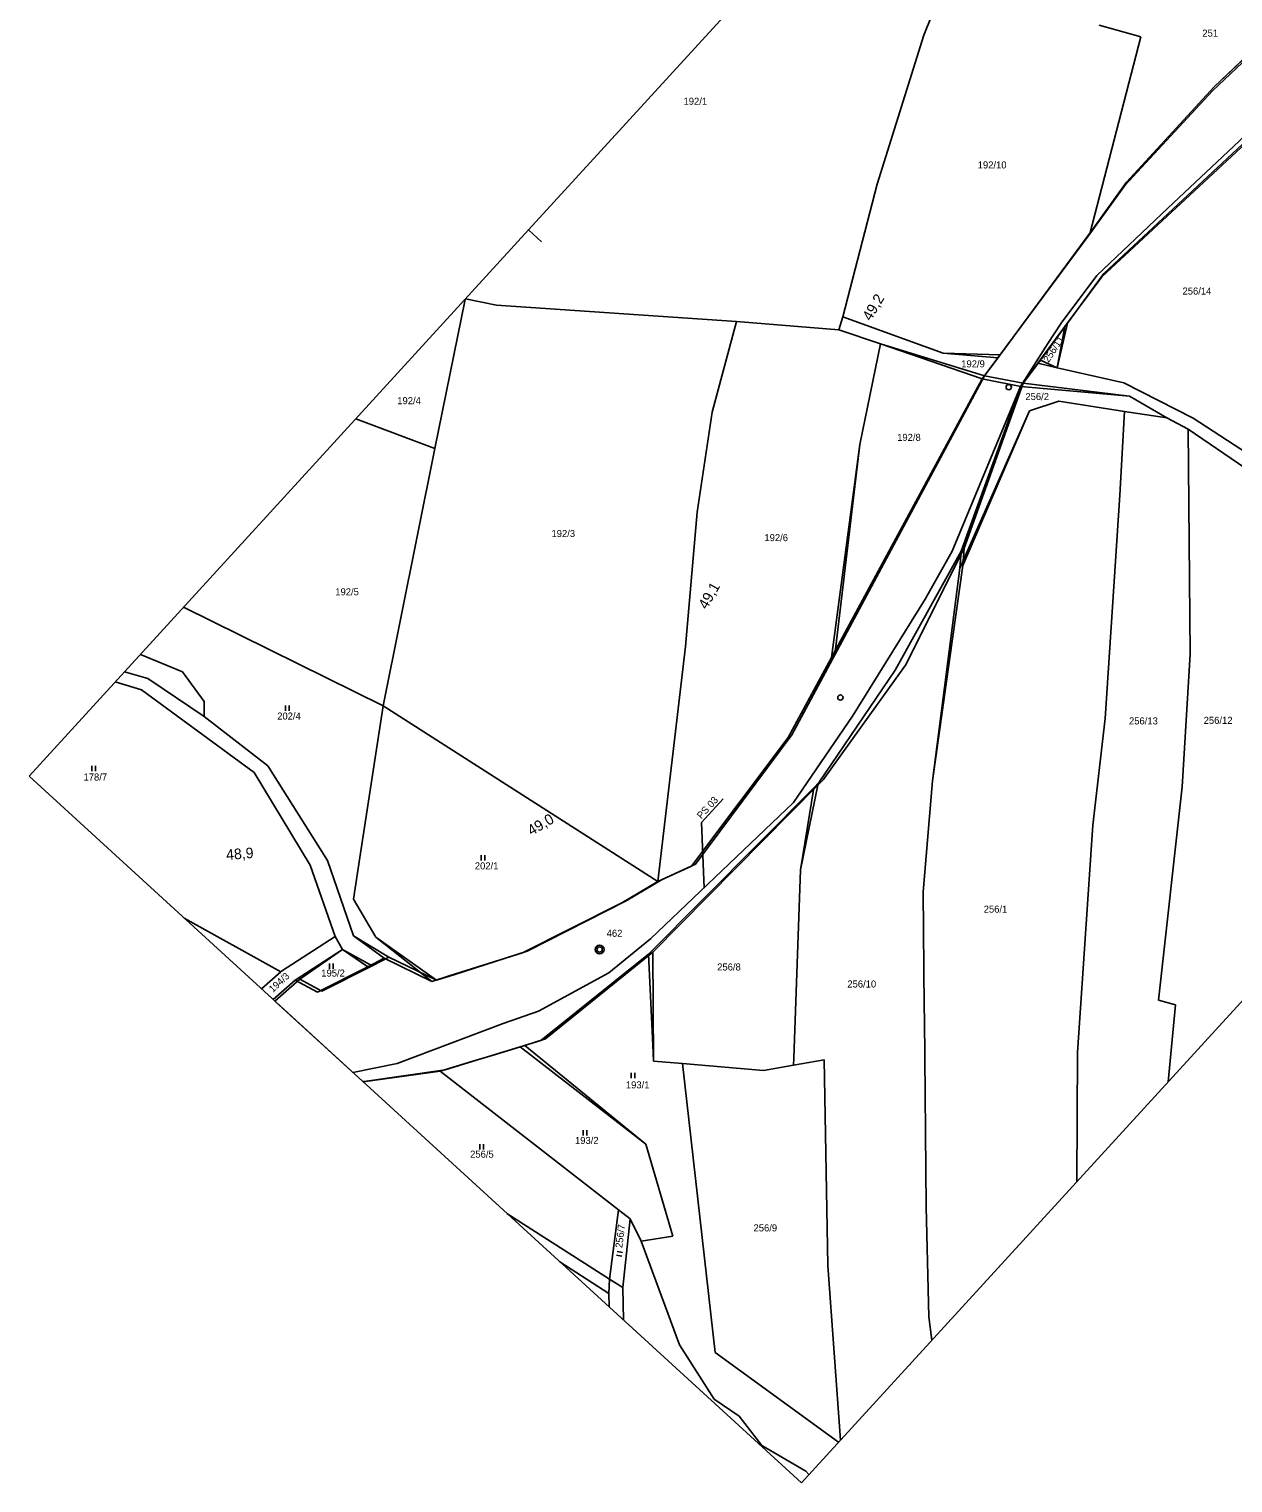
# Model space of a CAD drawing. Extents: x -678683 to -677755, y -1006946 to -1005971.
# Drawn here: x -678683 to -678341.4, y -1006946.3 to -1006533.9 of the extents above; entities that cross this region are included whole.
import ezdxf

# ---------------------------------------------------------------- set-up
doc = ezdxf.new("R2010")
doc.units = 0
for name, color, linetype in [('I_2_4_předběžný_vykres - SŽDC', 7, 'Continuous'), ('kilometráž - Vrstva 7', 7, 'Continuous'), ('koor - SSZT_nové', 7, 'Continuous'), ('MapaKN - Mladejov+Strelec_dosavani+nova_situace - Vrstva 1', 7, 'Continuous'), ('MapaKN - Mladejov+Strelec_dosavani+nova_situace - Vrstva 11', 7, 'Continuous'), ('MapaKN - Mladejov+Strelec_dosavani+nova_situace - Vrstva 18', 7, 'Continuous'), ('MapaKN - Mladejov+Strelec_dosavani+nova_situace - Vrstva 25', 7, 'Continuous'), ('MapaKN - původní vrstava 1', 7, 'Continuous'), ('popis', 7, 'Continuous'), ('ramy - Sekce lichá', 7, 'Continuous')]:
    doc.layers.add(name, color=color, linetype=linetype)

msp = doc.modelspace()

# ---------------------------------------------------------------- linework, layer by layer
at = {"layer": 'I_2_4_předběžný_vykres - SŽDC'}
for p, q in [((-678328.04, -1006532.61), (-678346.7, -1006550.29)), ((-678346.7, -1006550.29), (-678371.57, -1006577.31)), ((-678377.98, -1006603.23), (-678337.35, -1006565.27)), ((-678371.57, -1006577.31), (-678381.45, -1006591.04)), ((-678388.38, -1006617.35), (-678377.98, -1006603.23)), ((-678396.04, -1006627.76), (-678388.38, -1006617.35)), ((-678407.43, -1006626.27), (-678411.85, -1006632.26)), ((-678400.89, -1006634.35), (-678396.04, -1006627.76)), ((-678411.85, -1006632.26), (-678454.36, -1006711.39)), ((-678417.64, -1006681.12), (-678400.89, -1006634.35)), ((-678400.89, -1006634.35), (-678411.85, -1006632.26)), ((-678411.85, -1006632.26), (-678400.89, -1006634.35)), ((-678434.3, -1006714.32), (-678417.64, -1006681.12)), ((-678454.36, -1006711.39), (-678466.57, -1006734.1)), ((-678457.66, -1006746.82), (-678434.3, -1006714.32)), ((-678466.57, -1006734.1), (-678493.85, -1006770.72)), ((-678459.21, -1006748.39), (-678457.66, -1006746.82)), ((-678505.95, -1006795.71), (-678459.21, -1006748.39)), ((-678493.85, -1006770.72), (-678503.38, -1006775.08)), ((-678503.38, -1006775.08), (-678513.57, -1006781.17)), ((-678513.57, -1006781.17), (-678541.67, -1006795.44)), ((-678541.67, -1006795.44), (-678562.49, -1006802.11)), ((-678536.44, -1006820.34), (-678505.95, -1006795.71)), ((-678585.58, -1006799.58), (-678599.89, -1006806.81)), ((-678580.93, -1006797.11), (-678585.58, -1006799.58)), ((-678567.41, -1006803.68), (-678580.93, -1006797.11)), ((-678606.18, -1006803.39), (-678613.24, -1006809.59)), ((-678599.89, -1006806.81), (-678606.18, -1006803.39)), ((-678562.49, -1006802.11), (-678567.41, -1006803.68)), ((-678613.24, -1006809.59), (-678588.31, -1006832.39)), ((-678542.33, -1006822.15), (-678536.44, -1006820.34)), ((-678555.75, -1006826.28), (-678551.55, -1006824.99)), ((-678551.55, -1006824.99), (-678542.33, -1006822.15)), ((-678587.94, -1006832.39), (-678564.93, -1006829.1)), ((-678564.93, -1006829.1), (-678555.75, -1006826.28)), ((-678588.31, -1006832.39), (-678587.94, -1006832.39))]:
    msp.add_line(p, q, dxfattribs=at)
msp.add_lwpolyline([(-678381.45, -1006591.04), (-678381.96, -1006591.73), (-678407.43, -1006626.27)], dxfattribs=at)
at = {"layer": 'kilometráž - Vrstva 7'}
for centre, radius in [((-678405, -1006635.46), 0.75), ((-678452.78, -1006723.49), 0.75), ((-678521.09, -1006794.96), 1.25), ((-678521.09, -1006794.96), 0.752)]:
    msp.add_circle(centre, radius, dxfattribs=at)
at = {"layer": 'koor - SSZT_nové'}
for points in [[(-678506.62, -1006791.94), (-678466.12, -1006753.23), (-678449.33, -1006728.75), (-678428.75, -1006695.61), (-678421.07, -1006681.97), (-678401.67, -1006635.24), (-678393.87, -1006623.11), (-678390.13, -1006617.26), (-678380, -1006603.76), (-678359.84, -1006584.7), (-678339.66, -1006565.68), (-678276.52, -1006503.93), (-678276.52, -1006503.93)], [(-678591.08, -1006829.86), (-678578.56, -1006827.33), (-678548.42, -1006815.94), (-678538.41, -1006812.42), (-678518.43, -1006801.56), (-678506.62, -1006791.94), (-678506.62, -1006791.94)]]:
    msp.add_lwpolyline(points, dxfattribs=at)
at = {"layer": 'MapaKN - Mladejov+Strelec_dosavani+nova_situace - Vrstva 1'}
for points in [[(-678420.43, -1006513.99), (-678429.12, -1006535.58)], [(-678379.35, -1006532.79), (-678367.5, -1006536.07)], [(-678429.12, -1006535.58), (-678442.37, -1006577.92)], [(-678367.5, -1006536.07), (-678382.03, -1006592)], [(-678442.37, -1006577.92), (-678452.11, -1006615.47)], [(-678559.26, -1006610.55), (-678567.8, -1006652.87)], [(-678550.36, -1006612.19), (-678559.15, -1006610.43)], [(-678482.29, -1006616.83), (-678550.36, -1006612.19)], [(-678452.11, -1006615.47), (-678453.19, -1006619.16)], [(-678423.65, -1006625.83), (-678452.11, -1006615.47)], [(-678482.29, -1006616.83), (-678489.11, -1006642.57)], [(-678453.19, -1006619.16), (-678482.29, -1006616.83)], [(-678453.19, -1006619.16), (-678441.4, -1006623.21)], [(-678441.4, -1006623.21), (-678447.23, -1006651.72)], [(-678372.38, -1006634.27), (-678391.25, -1006629.93)], [(-678352.67, -1006644.27), (-678372.38, -1006634.27)], [(-678390.75, -1006639.42), (-678399.16, -1006642.13)], [(-678372.18, -1006642.32), (-678390.75, -1006639.42)], [(-678370.74, -1006638.02), (-678360.18, -1006644.19)], [(-678489.11, -1006642.57), (-678493.38, -1006670.87)], [(-678373.53, -1006666.09), (-678372.18, -1006642.32)], [(-678360.18, -1006644.19), (-678372.18, -1006642.32)], [(-678354.06, -1006647.41), (-678360.18, -1006644.19)], [(-678337.28, -1006654.25), (-678352.67, -1006644.27)], [(-678567.8, -1006652.87), (-678590.28, -1006644.46)], [(-678353.55, -1006711.22), (-678354.06, -1006647.41)], [(-678354.06, -1006647.41), (-678337.76, -1006658.53)], [(-678567.8, -1006652.87), (-678582.53, -1006725.83)], [(-678377.6, -1006729.48), (-678373.53, -1006666.09)], [(-678493.38, -1006670.87), (-678496.7, -1006709.02)], [(-678639.15, -1006697.89), (-678582.53, -1006725.83)], [(-678496.7, -1006709.02), (-678504.57, -1006775.64)], [(-678639.46, -1006716.2), (-678651.38, -1006711.26)], [(-678355.8, -1006748.81), (-678353.55, -1006711.22)], [(-678655.87, -1006716.16), (-678649.31, -1006718.06)], [(-678649.31, -1006718.06), (-678633.3, -1006728.9)], [(-678633.27, -1006724.57), (-678639.46, -1006716.2)], [(-678658.53, -1006719.07), (-678651.04, -1006721.27)], [(-678651.04, -1006721.27), (-678619.06, -1006744.74)], [(-678633.3, -1006728.9), (-678633.27, -1006724.57)], [(-678582.53, -1006725.83), (-678589.14, -1006768.88)], [(-678582.53, -1006725.83), (-678504.57, -1006775.64)], [(-678633.3, -1006728.9), (-678615.21, -1006742.84)], [(-678381.19, -1006759.69), (-678377.6, -1006729.48)], [(-678615.21, -1006742.84), (-678598.31, -1006769.67)], [(-678619.06, -1006744.74), (-678603.23, -1006770.99)], [(-678426.68, -1006747.13), (-678429.29, -1006778.6)], [(-678362.53, -1006809.3), (-678355.8, -1006748.81)], [(-678385.49, -1006824.2), (-678381.19, -1006759.69)], [(-678603.23, -1006770.99), (-678596.1, -1006791.26)], [(-678598.31, -1006769.67), (-678590.92, -1006791.09)], [(-678589.14, -1006768.88), (-678590.95, -1006780.65)], [(-678465.97, -1006825.71), (-678464.06, -1006772.32)], [(-678429.29, -1006778.6), (-678429.05, -1006811.35)], [(-678590.95, -1006780.65), (-678584.59, -1006791.47)], [(-678611.57, -1006801.32), (-678638.98, -1006786.04)], [(-678596.1, -1006791.26), (-678611.34, -1006801.12)], [(-678594.01, -1006794.95), (-678596.1, -1006791.26)], [(-678506.03, -1006822.05), (-678507.21, -1006796.26)], [(-678611.57, -1006801.32), (-678617.05, -1006806.1)], [(-678611.34, -1006801.12), (-678611.57, -1006801.32)], [(-678357.73, -1006810.61), (-678362.53, -1006809.3)], [(-678429.05, -1006811.35), (-678428.88, -1006814.85)], [(-678359.8, -1006832.53), (-678357.73, -1006810.61)], [(-678428.43, -1006867.92), (-678428.88, -1006814.85)], [(-678507.96, -1006850.17), (-678543.67, -1006822.58)], [(-678505.82, -1006826.67), (-678506.03, -1006822.05)], [(-678465.97, -1006825.71), (-678466.07, -1006827.77)], [(-678385.66, -1006860.8), (-678385.49, -1006824.2)], [(-678566.3, -1006829.46), (-678515.73, -1006868.76)], [(-678497.6, -1006827.29), (-678505.82, -1006826.67)], [(-678488.35, -1006909.3), (-678497.6, -1006827.29)], [(-678474.56, -1006829.3), (-678497.6, -1006827.29)], [(-678466.07, -1006827.77), (-678474.56, -1006829.3)], [(-678457.4, -1006826.21), (-678466.07, -1006827.77)], [(-678457.31, -1006831.43), (-678457.4, -1006826.21)], [(-678456.35, -1006884.57), (-678457.31, -1006831.43)], [(-678500.3, -1006876.27), (-678507.96, -1006850.17)], [(-678547.38, -1006869.83), (-678518.29, -1006888.42)], [(-678518.29, -1006888.42), (-678515.73, -1006868.76)], [(-678515.73, -1006868.76), (-678512.38, -1006871.37)], [(-678427.67, -1006899.18), (-678428.43, -1006867.92)], [(-678512.38, -1006871.37), (-678514.5, -1006890.81)], [(-678512.38, -1006871.37), (-678509.3, -1006877.66)], [(-678509.3, -1006877.66), (-678500.3, -1006876.27)], [(-678509.3, -1006877.66), (-678498.46, -1006907.11)], [(-678518.51, -1006892.56), (-678532.42, -1006883.51)], [(-678452.76, -1006934.15), (-678456.35, -1006884.57)], [(-678518.51, -1006892.56), (-678518.29, -1006888.42)], [(-678518.29, -1006888.42), (-678514.5, -1006890.81)], [(-678514.5, -1006890.81), (-678514.28, -1006900.11)], [(-678518.4, -1006896.34), (-678518.51, -1006892.56)], [(-678426.83, -1006905.81), (-678427.67, -1006899.18)], [(-678488.59, -1006922.49), (-678498.46, -1006907.11)], [(-678453.3, -1006934.74), (-678488.35, -1006909.3)], [(-678481.46, -1006927.33), (-678488.59, -1006922.49)], [(-678475.05, -1006935.68), (-678481.46, -1006927.33)], [(-678462.59, -1006942.93), (-678475.05, -1006935.68)], [(-678461.68, -1006943.91), (-678462.59, -1006942.93)]]:
    msp.add_lwpolyline(points, dxfattribs=at)
at = {"layer": 'MapaKN - Mladejov+Strelec_dosavani+nova_situace - Vrstva 11'}
for p, q in [((-678396.04, -1006627.76), (-678388.38, -1006617.35)), ((-678411.85, -1006632.26), (-678441.4, -1006623.21)), ((-678407.43, -1006626.27), (-678423.65, -1006625.83)), ((-678454.36, -1006711.39), (-678447.23, -1006651.72)), ((-678417.99, -1006686), (-678426.68, -1006747.13)), ((-678580.93, -1006797.11), (-678590.92, -1006791.09)), ((-678584.59, -1006791.47), (-678567.41, -1006803.68)), ((-678505.95, -1006795.71), (-678505.82, -1006826.67)), ((-678542.33, -1006822.15), (-678507.96, -1006850.17))]:
    msp.add_line(p, q, dxfattribs=at)
for points in [[(-678346.7, -1006550.29), (-678328.04, -1006532.61)], [(-678371.57, -1006577.31), (-678346.7, -1006550.29)], [(-678337.35, -1006565.27), (-678377.98, -1006603.23)], [(-678381.45, -1006591.04), (-678371.57, -1006577.31)], [(-678407.43, -1006626.27), (-678381.45, -1006591.04)], [(-678377.98, -1006603.23), (-678388.38, -1006617.35)], [(-678388.38, -1006617.35), (-678391.25, -1006629.93)], [(-678411.85, -1006632.26), (-678407.43, -1006626.27)], [(-678396.04, -1006627.76), (-678400.89, -1006634.35)], [(-678391.25, -1006629.93), (-678396.04, -1006627.76)], [(-678454.36, -1006711.39), (-678411.85, -1006632.26)], [(-678400.89, -1006634.35), (-678417.64, -1006681.12)], [(-678400.89, -1006634.35), (-678411.85, -1006632.26)], [(-678400.89, -1006634.35), (-678370.74, -1006638.02)], [(-678417.99, -1006686), (-678399.16, -1006642.13)], [(-678417.64, -1006681.12), (-678434.3, -1006714.32)], [(-678417.64, -1006681.12), (-678417.99, -1006686)], [(-678466.57, -1006734.1), (-678454.36, -1006711.39)], [(-678457.66, -1006746.82), (-678434.3, -1006714.32)], [(-678493.85, -1006770.72), (-678466.57, -1006734.1)], [(-678457.66, -1006746.82), (-678459.21, -1006748.39)], [(-678459.21, -1006748.39), (-678505.95, -1006795.71)], [(-678459.21, -1006748.39), (-678464.06, -1006772.32)], [(-678503.38, -1006775.08), (-678493.85, -1006770.72)], [(-678513.57, -1006781.17), (-678503.38, -1006775.08)], [(-678541.67, -1006795.44), (-678513.57, -1006781.17)], [(-678606.18, -1006803.39), (-678594.01, -1006794.95), (-678585.58, -1006799.58)], [(-678562.49, -1006802.11), (-678541.67, -1006795.44)], [(-678505.95, -1006795.71), (-678536.44, -1006820.34)], [(-678599.89, -1006806.81), (-678585.58, -1006799.58)], [(-678585.58, -1006799.58), (-678580.93, -1006797.11)], [(-678580.93, -1006797.11), (-678567.41, -1006803.68)], [(-678613.24, -1006809.59), (-678606.18, -1006803.39)], [(-678606.18, -1006803.39), (-678599.89, -1006806.81)], [(-678567.41, -1006803.68), (-678562.49, -1006802.11)], [(-678536.44, -1006820.34), (-678542.33, -1006822.15)], [(-678551.55, -1006824.99), (-678555.75, -1006826.28)], [(-678542.33, -1006822.15), (-678551.55, -1006824.99)], [(-678564.93, -1006829.1), (-678587.94, -1006832.39)], [(-678555.75, -1006826.28), (-678564.93, -1006829.1)], [(-678587.94, -1006832.39), (-678588.31, -1006832.39)]]:
    msp.add_lwpolyline(points, dxfattribs=at)
at = {"layer": 'MapaKN - Mladejov+Strelec_dosavani+nova_situace - Vrstva 25'}
for points in [[(-678610.25, -1006727.27), (-678610.25, -1006725.77)], [(-678609.21, -1006727.27), (-678609.21, -1006725.77)], [(-678665.17, -1006744.38), (-678665.17, -1006742.88)], [(-678664.13, -1006744.38), (-678664.13, -1006742.88)], [(-678554.71, -1006769.7), (-678554.71, -1006768.2)], [(-678553.67, -1006769.7), (-678553.67, -1006768.2)], [(-678597.7, -1006800.41), (-678597.7, -1006798.91)], [(-678596.66, -1006800.41), (-678596.66, -1006798.91)], [(-678512.1, -1006831.48), (-678512.1, -1006829.98)], [(-678511.06, -1006831.48), (-678511.06, -1006829.98)], [(-678525.8, -1006847.74), (-678525.8, -1006846.24)], [(-678524.76, -1006847.74), (-678524.76, -1006846.24)], [(-678555.1, -1006851.7), (-678555.1, -1006850.2)], [(-678554.06, -1006851.7), (-678554.06, -1006850.2)], [(-678514.81, -1006881.92), (-678516.29, -1006881.67)], [(-678514.64, -1006880.9), (-678516.11, -1006880.65)]]:
    msp.add_lwpolyline(points, dxfattribs=at)
at = {"layer": 'MapaKN - původní vrstava 1'}
for points in [[(-678328.43, -1006533.75), (-678347.15, -1006551.37)], [(-678347.15, -1006551.37), (-678372.11, -1006578.3)], [(-678337.85, -1006566.38), (-678378.6, -1006604.2)], [(-678372.11, -1006578.3), (-678382.03, -1006592)], [(-678382.03, -1006592), (-678408.13, -1006627.15)], [(-678378.6, -1006604.2), (-678389.05, -1006618.29)], [(-678389.05, -1006618.29), (-678396.74, -1006628.67)], [(-678389.05, -1006618.29), (-678391.25, -1006629.93)], [(-678441.4, -1006623.21), (-678412.57, -1006633.12)], [(-678408.13, -1006627.15), (-678423.65, -1006625.83)], [(-678408.13, -1006627.15), (-678412.57, -1006633.12)], [(-678396.74, -1006628.67), (-678401.62, -1006635.25)], [(-678391.25, -1006629.93), (-678396.74, -1006628.67)], [(-678455.34, -1006712.11), (-678412.57, -1006633.12)], [(-678401.62, -1006635.25), (-678418.52, -1006681.96)], [(-678412.57, -1006633.12), (-678401.62, -1006635.25)], [(-678401.62, -1006635.25), (-678370.74, -1006638.02)], [(-678399.16, -1006642.13), (-678418.89, -1006686.84)], [(-678447.23, -1006651.72), (-678455.34, -1006712.11)], [(-678418.52, -1006681.96), (-678437.25, -1006715.74)], [(-678418.89, -1006686.84), (-678418.52, -1006681.96)], [(-678418.89, -1006686.84), (-678426.68, -1006747.13)], [(-678467.62, -1006734.78), (-678455.34, -1006712.11)], [(-678437.25, -1006715.74), (-678458.76, -1006747.53)], [(-678495.02, -1006771.31), (-678467.62, -1006734.78)], [(-678460.31, -1006749.09), (-678507.21, -1006796.26)], [(-678464.06, -1006772.32), (-678460.31, -1006749.09)], [(-678458.76, -1006747.53), (-678460.31, -1006749.09)], [(-678504.57, -1006775.64), (-678495.02, -1006771.31)], [(-678504.57, -1006775.64), (-678514.78, -1006781.69)], [(-678514.78, -1006781.69), (-678542.93, -1006795.87)], [(-678590.92, -1006791.09), (-678582.19, -1006797.41)], [(-678584.59, -1006791.47), (-678568.69, -1006804.03)], [(-678607.46, -1006803.61), (-678594.01, -1006794.95)], [(-678594.01, -1006794.95), (-678586.85, -1006799.87)], [(-678542.93, -1006795.87), (-678563.77, -1006802.47)], [(-678507.21, -1006796.26), (-678537.78, -1006820.79)], [(-678601.18, -1006807.05), (-678586.85, -1006799.87)], [(-678582.19, -1006797.41), (-678586.85, -1006799.87)], [(-678568.69, -1006804.03), (-678582.19, -1006797.41)], [(-678613.76, -1006809.11), (-678607.46, -1006803.61)], [(-678607.46, -1006803.61), (-678601.18, -1006807.05)], [(-678563.77, -1006802.47), (-678568.69, -1006804.03)], [(-678537.78, -1006820.79), (-678543.67, -1006822.58)], [(-678552.9, -1006825.39), (-678557.11, -1006826.67)], [(-678543.67, -1006822.58), (-678552.9, -1006825.39)], [(-678588.18, -1006832.51), (-678566.3, -1006829.46)], [(-678557.11, -1006826.67), (-678566.3, -1006829.46)]]:
    msp.add_lwpolyline(points, dxfattribs=at)
at = {"layer": 'popis'}
msp.add_lwpolyline([(-678491.42, -1006777.57), (-678492.18, -1006758.9), (-678486.05, -1006752.2)], dxfattribs=at)
at = {"layer": 'ramy - Sekce lichá'}
for p, q in [((-678541.24, -1006590.84), (-678399.5, -1006435.89)), ((-678682.98, -1006745.8), (-678541.24, -1006590.84)), ((-678541.24, -1006590.84), (-678537.55, -1006594.22)), ((-678463.83, -1006946.26), (-678682.98, -1006745.8)), ((-678463.83, -1006946.26), (-678322.09, -1006791.3))]:
    msp.add_line(p, q, dxfattribs=at)

# ---------------------------------------------------------------- texts
at = {"layer": 'kilometráž - Vrstva 7'}
for s, rotation, p in [('49,2', 59.3119, (-678444.16, -1006616.89)), ('49,1', 60.1002, (-678490.7, -1006698.67)), ('49,0', 30.5229, (-678540.45, -1006762.77)), ('48,9', 4.5291, (-678626.96, -1006769.59))]:
    msp.add_text(s, height=3, rotation=rotation, dxfattribs=at).set_placement(p)
at = {"layer": 'MapaKN - Mladejov+Strelec_dosavani+nova_situace - Vrstva 18'}
for s, p in [('251', (-678350.07, -1006536.04)), ('192/1', (-678497.28, -1006555.36)), ('192/10', (-678413.81, -1006573.42)), ('256/14', (-678355.7, -1006609.19)), ('192/9', (-678418.48, -1006629.85)), ('192/4', (-678578.5, -1006640.29)), ('256/2', (-678400.28, -1006639.12)), ('192/8', (-678436.67, -1006650.7)), ('192/3', (-678534.74, -1006677.96)), ('192/6', (-678474.33, -1006679.13)), ('192/5', (-678596.09, -1006694.5)), ('202/4', (-678612.57, -1006729.74)), ('256/13', (-678370.88, -1006731.12)), ('256/12', (-678349.7, -1006730.96)), ('178/7', (-678667.53, -1006747.03)), ('202/1', (-678556.5, -1006772.23)), ('256/1', (-678412.11, -1006784.51)), ('462', (-678519.09, -1006791.35)), ('195/2', (-678600.07, -1006802.64)), ('256/8', (-678487.73, -1006800.91)), ('256/10', (-678450.8, -1006805.74)), ('193/1', (-678513.64, -1006834.35)), ('193/2', (-678528.07, -1006850.11)), ('256/5', (-678557.83, -1006854.02)), ('256/9', (-678477.42, -1006874.92))]:
    msp.add_text(s, height=2, dxfattribs=at).set_placement(p)
for s, rotation, p in [('256/11', 57.2005, (-678393.68, -1006628.65)), ('194/3', 42.5003, (-678613.82, -1006807.28)), ('256/7', 83.0007, (-678514.67, -1006879.7))]:
    msp.add_text(s, height=2, rotation=rotation, dxfattribs=at).set_placement(p)
at = {"layer": 'popis'}
msp.add_text('PS 03', height=2, rotation=47.5497, dxfattribs=at).set_placement((-678492.22, -1006758.06))

doc.saveas('drawing.dxf')
